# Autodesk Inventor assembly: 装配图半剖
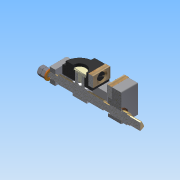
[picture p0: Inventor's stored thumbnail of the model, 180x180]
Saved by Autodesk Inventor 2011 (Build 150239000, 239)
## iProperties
Created: 2013-12
Part Number: 装配图半剖
Document SubType Name: Assembly
Designer: Administrator
Author: Administrator
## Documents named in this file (11)
- C:\Documents and Settings\Administrator\桌面\机械制图\虎钳\装配图半剖.iam
- C:\Documents and Settings\Administrator\桌面\机械制图\虎钳\钳座.ipt
- C:\Documents and Settings\Administrator\桌面\机械制图\虎钳\垫圈.ipt
- C:\Documents and Settings\Administrator\桌面\机械制图\虎钳\方块螺母.ipt
- C:\Documents and Settings\Administrator\桌面\机械制图\虎钳\护口板.ipt
- C:\Documents and Settings\Administrator\桌面\机械制图\虎钳\活动钳块.ipt
- C:\Documents and Settings\Administrator\桌面\机械制图\虎钳\螺钉 GB_T 68 M8 x 12.ipt
- C:\Documents and Settings\Administrator\桌面\机械制图\虎钳\螺钉.ipt
- C:\Documents and Settings\Administrator\桌面\机械制图\虎钳\螺杆.ipt
- C:\Documents and Settings\Administrator\桌面\机械制图\虎钳\螺母 GB_T 6170 M10.ipt
- C:\Documents and Settings\Administrator\桌面\机械制图\虎钳\平垫圈 GB_T 97.1 10.ipt
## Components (15 placed, 10 different names)
1. 钳座:1 — 插入:1, 插入:3, 配合:1, 表面齐平:1, 表面齐平:2, 配合:7, 表面齐平:4
2. 垫圈:1 — 插入:1, 插入:2
3. 护口板:1 — 配合:1, 表面齐平:1, 表面齐平:2, 配合:8, 配合:9, 相切:2, 配合:11, 相切:4
4. 活动钳块:1 — 配合:2, 配合:3, 表面齐平:3, 配合:7, 表面齐平:4, 配合:12
5. 螺钉 GB_T 68 M8 x 12:1 — 配合:4, 配合:5, 配合:6, 相切:1
6. 螺钉:1 — 插入:5
7. 螺杆:1 — 插入:2, 配合:13
8. 螺母 GB_T 6170 M10:1 — 插入:4, 插入:6
9. 平垫圈 GB_T 97.1 10:1 — 插入:3, 插入:4
10. 护口板:2 — 配合:2, 配合:3, 表面齐平:3, 配合:4, 配合:5, 配合:6, 相切:1, 配合:8, 配合:10, 相切:3
11. 螺钉 GB_T 68 M8 x 12:2 — 配合:11, 相切:4
12. 螺钉 GB_T 68 M8 x 12:3 — 配合:10, 相切:3
13. 螺钉 GB_T 68 M8 x 12:4 — 配合:9, 相切:2
14. 方块螺母:1 — 配合:12, 配合:13, 插入:5
15. 螺母 GB_T 6170 M10:2 — 插入:6
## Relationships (27: Mate 13, Insert 6, Flush 4, Tangent 4)
- 插入:1 [Insert]: 钳座:1 ↔ 垫圈:1
- 插入:2 [Insert]: 垫圈:1 ↔ 螺杆:1
- 插入:3 [Insert]: 钳座:1 ↔ 平垫圈 GB_T 97.1 10:1
- 插入:4 [Insert]: 螺母 GB_T 6170 M10:1 ↔ 平垫圈 GB_T 97.1 10:1
- 配合:1 [Mate]: 钳座:1 ↔ 护口板:1
- 表面齐平:1 [Flush]: 钳座:1 ↔ 护口板:1
- 表面齐平:2 [Flush]: 钳座:1 ↔ 护口板:1
- 配合:2 [Mate]: 活动钳块:1 ↔ 护口板:2
- 配合:3 [Mate]: 活动钳块:1 ↔ 护口板:2
- 表面齐平:3 [Flush]: 活动钳块:1 ↔ 护口板:2
- 配合:4 [Mate]: 螺钉 GB_T 68 M8 x 12:1 ↔ 护口板:2
- 配合:5 [Mate]: 螺钉 GB_T 68 M8 x 12:1 ↔ 护口板:2
- 配合:6 [Mate]: 螺钉 GB_T 68 M8 x 12:1 ↔ 护口板:2
- 相切:1 [Tangent]: 螺钉 GB_T 68 M8 x 12:1 ↔ 护口板:2
- 配合:7 [Mate]: 钳座:1 ↔ 活动钳块:1
- 表面齐平:4 [Flush]: 钳座:1 ↔ 活动钳块:1
- 配合:8 [Mate]: 护口板:1 ↔ 护口板:2
- 配合:9 [Mate]: 护口板:1 ↔ 螺钉 GB_T 68 M8 x 12:4
- 相切:2 [Tangent]: 护口板:1 ↔ 螺钉 GB_T 68 M8 x 12:4
- 配合:10 [Mate]: 护口板:2 ↔ 螺钉 GB_T 68 M8 x 12:3
- 相切:3 [Tangent]: 护口板:2 ↔ 螺钉 GB_T 68 M8 x 12:3
- 配合:11 [Mate]: 护口板:1 ↔ 螺钉 GB_T 68 M8 x 12:2
- 相切:4 [Tangent]: 护口板:1 ↔ 螺钉 GB_T 68 M8 x 12:2
- 配合:12 [Mate]: 活动钳块:1 ↔ 方块螺母:1
- 配合:13 [Mate]: 螺杆:1 ↔ 方块螺母:1
- 插入:5 [Insert]: 螺钉:1 ↔ 方块螺母:1
- 插入:6 [Insert]: 螺母 GB_T 6170 M10:1 ↔ 螺母 GB_T 6170 M10:2
